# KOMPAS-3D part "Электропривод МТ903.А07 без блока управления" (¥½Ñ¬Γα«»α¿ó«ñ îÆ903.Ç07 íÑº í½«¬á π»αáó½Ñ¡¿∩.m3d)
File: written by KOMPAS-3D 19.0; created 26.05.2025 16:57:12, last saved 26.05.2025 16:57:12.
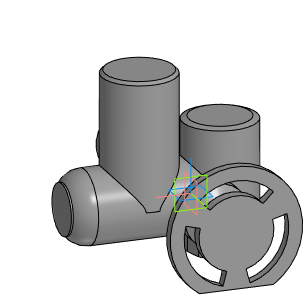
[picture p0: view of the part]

Document properties: Полное имя файла: E:\Dendor Работа Сачек\3D для проекитирвщиков\3.4 Электропривод МТ903.А\stp_Тип МТ903.А без блока управления\Электропривод МТ903.А07 без блока управления.m3d

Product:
- Part/product: Электропривод МТ903.А07 без блока управления

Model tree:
1. Операция без истории:1  (labels: Электропривод МТ903.А07 без блока управления)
